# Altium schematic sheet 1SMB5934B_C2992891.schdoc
size 127 x 101 mm
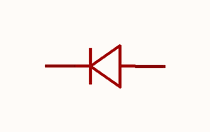
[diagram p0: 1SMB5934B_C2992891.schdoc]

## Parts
D?  1smb5934b_c2992891  [SMB_L4.6-W3.6-LS5.3-RD]  (value not drawn)

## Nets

Not connected (* = marked no-connect by the designer): D? 1(K) 2(A)

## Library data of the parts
D? = 1smb5934b_c2992891: 二极管配置:1个独立式;稳压值(标称值):24V;稳压值(范围值):22.8V~25.2V;耗散功率(Pd):3W;; Manufacturer: MDD(辰达半导体); AddInBom: yes; ModelId: 5e8926c661484ff2a35b83e5ae62aeb9; ModelTransform: 212.598,141.732,0,0,0,0,0,0,0; Diode Configuration: 1个独立式; Zener Voltage(Nom): 24V; Reverse Leakage Current (Ir): 1uA@18.2V; Pd - Power Dissipation: 3W; Impedance(Zzt): 19Ω; Impedance(Zzk): 700Ω; Operating Junction Temperature Range: -55℃~+150℃; Tolerance: ±5%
